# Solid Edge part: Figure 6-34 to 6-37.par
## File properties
Author: Ashutosh-CADCIM
Template: Iso Metric Part.par
Last saved by: Ashutosh-CADCIM
Revision: 1
Application: Solid Edge
Accuracy: 0.990
Username: Ashutosh-CADCIM
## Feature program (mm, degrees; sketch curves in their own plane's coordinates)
sketch for "unnamed Protrusion 1" plane through (0, 0, 0) normal (0, -1, 0) x-axis (1, 0, 0)
  line (0, 100) -> (0, 0)
  line (0, 0) -> (100, 0)
  line (100, 0) -> (100, 20)
  line (100, 20) -> (20, 20)
  line (20, 20) -> (20, 100)
  line (20, 100) -> (0, 100)
  dimension (linear) = 100
extrude "unnamed Protrusion 1" add finite 100 symmetric
sketch for "ExtrudedCutout_1" plane through (60, 0, 20) normal (0, 0, 1) x-axis (0, 1, 0)
  line (10, -20) -> (-10, -20)
  line (-10, -20) -> (-10, 20)
  line (-10, 20) -> (10, 20)
  line (10, 20) -> (10, -20)
  dimension (linear) = 10
  dimension (linear) = 10
extrude "ExtrudedCutout_1" cut finite 116.9458 symmetric
sketch for "ExtrudedCutout_2" plane through (10, 0, 100) normal (0, 0, 1) x-axis (0, 1, 0)
  line (-60.7863, 14.3845) -> (60.7863, 14.3845)
  line (60.7863, 14.3845) -> (60.7863, -14.3845)
  line (60.7863, -14.3845) -> (-60.7863, -14.3845)
  line (-60.7863, -14.3845) -> (-60.7863, 14.3845)
extrude "ExtrudedCutout_2" cut finite 31.4628 symmetric
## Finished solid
Body 1: solid body, 12 faces, 30 edges, 20 vertices.
  Faces by surface: plane 12
  Edges by curve: line 30
Bounding box of the edges (mm): 100.000 x 100.000 x 84.269, from (0, -50, 0) to (100, 50, 84.2686).
Planar faces by outward normal: +x 3, +y 2, +z 2, -x 2, -y 2, -z 1
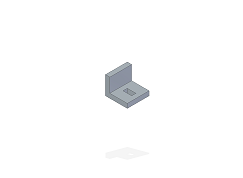
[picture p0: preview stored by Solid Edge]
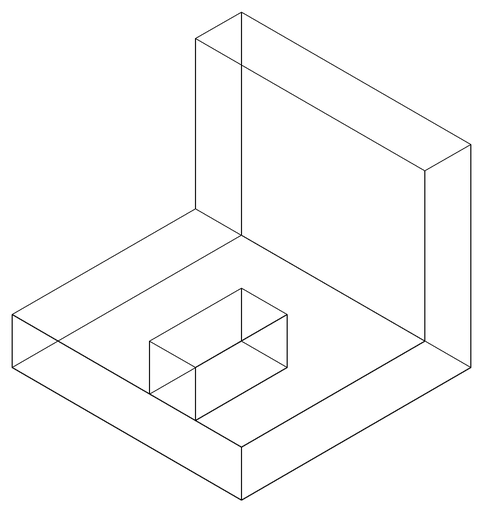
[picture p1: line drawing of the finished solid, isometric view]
